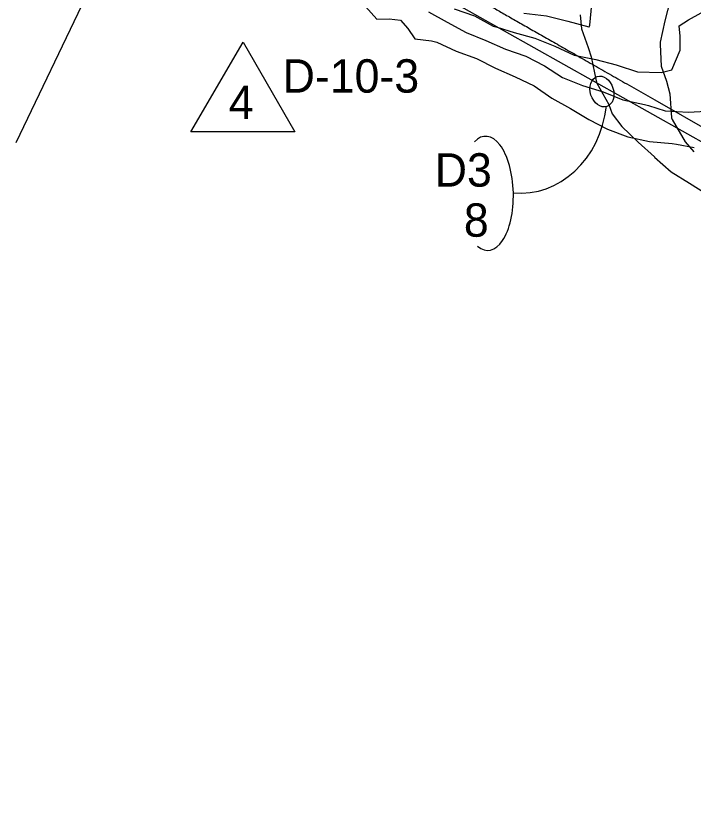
# Model space of a CAD drawing. Extents: x 1638506 to 1658005, y 834807 to 846788.
# Drawn here: x 1640164.8 to 1640408.1, y 842236.7 to 842523.2 of the extents above; entities that cross this region are included whole.
import ezdxf

# ---------------------------------------------------------------- set-up
doc = ezdxf.new("R2010")
doc.units = 0
for name, color, linetype in [('Default', 7, 'Continuous'), ('Old_Level_1', 7, 'Continuous'), ('Old_Level_2', 7, 'Continuous'), ('Scratch_Level_0', 7, 'Continuous')]:
    doc.layers.add(name, color=color, linetype=linetype)

msp = doc.modelspace()

# ---------------------------------------------------------------- linework, layer by layer
at = {"layer": 'Default'}
msp.add_line((1640314.09, 842532.64), (1640637.56, 842350.59), dxfattribs=at)
msp.add_lwpolyline([(1640264.98, 842481.57), (1640227.59, 842481.57), (1640246.42, 842513.84)], close=True, dxfattribs=at)
msp.add_ellipse((1640375.35, 842496.07), major_axis=(-1.72, 5.4), ratio=0.730797, dxfattribs=at)
for centre, major_axis, ratio, start_param, end_param in [((1640347.29, 842494.04), (3.78, 34.34), 0.862742, 3.141593, 4.712389), ((1640333.94, 842459.47), (0.49, -20.52), 0.466223, 1.570796, 3.572354), ((1640333.94, 842459.47), (0.49, -20.52), 0.466223, 5.884886, 7.853982)]:
    msp.add_ellipse(centre, major_axis=major_axis, ratio=ratio, start_param=start_param, end_param=end_param, dxfattribs=at)
at = {"layer": 'Old_Level_1'}
for points in [[(1640408.34, 842538.91), (1640403.52, 842535.72), (1640399.85, 842528.99), (1640397.93, 842521.45), (1640396.24, 842513.79), (1640396.26, 842513.01), (1640396.66, 842505.16), (1640398.51, 842499.74), (1640399.73, 842495.28), (1640400.3, 842486.58), (1640400.57, 842486.05), (1640405.23, 842477.95), (1640408.35, 842474.38)], [(1640367.46, 842523.66), (1640367.95, 842518.54), (1640370.42, 842511.9), (1640371.43, 842508.48), (1640373.26, 842499.89), (1640373.45, 842499.1), (1640377.77, 842491.46), (1640379.06, 842488.04), (1640382.51, 842483.53), (1640388.3, 842477.84), (1640394.21, 842472.54), (1640394.25, 842472.5), (1640400.24, 842467.24), (1640406.77, 842463.14), (1640413.31, 842459.07)]]:
    msp.add_lwpolyline(points, dxfattribs=at)
at = {"layer": 'Old_Level_2'}
for p, q in [((1640319.78, 842802.51), (1640164.82, 842477.58)), ((1640394.38, 842493.02), (1640843.22, 842236.75))]:
    msp.add_line(p, q, dxfattribs=at)
msp.add_open_spline([(1640269.4, 842563.39), (1640311.31, 842540.44), (1640352.83, 842516.74), (1640394.38, 842493.02)], degree=2, dxfattribs=at)
at = {"layer": 'Scratch_Level_0'}
for points in [[(1640290.38, 842526.57), (1640294.52, 842522.1), (1640298.94, 842522.13), (1640302.93, 842521.71), (1640305.57, 842518.68), (1640308.1, 842515.05), (1640314.13, 842514.24), (1640316.04, 842513.75), (1640323.01, 842510.56), (1640330.24, 842507.89), (1640337.06, 842504.44), (1640344.11, 842501.4), (1640350.99, 842498.06), (1640357.32, 842493.65), (1640364, 842489.91), (1640370.6, 842486.02), (1640377.39, 842482.5), (1640384.63, 842479.83), (1640392.38, 842478.16), (1640400.58, 842477.36), (1640402.08, 842477.17), (1640408.49, 842475.99)], [(1640322.3, 842525.81), (1640329.58, 842523.22), (1640336.3, 842519.56), (1640337.67, 842519.25), (1640343.75, 842517.31), (1640351.27, 842515.19), (1640358.42, 842512.36), (1640365.39, 842509.18), (1640373.17, 842507.57), (1640380.4, 842505.67), (1640380.75, 842505.57), (1640388.1, 842503.11), (1640396.59, 842502.87), (1640400.5, 842503.85), (1640403.46, 842510.94), (1640403.39, 842515.96), (1640403.13, 842519.73), (1640406.44, 842521.82), (1640410.95, 842524.29)], [(1640370.75, 842519.31), (1640370.97, 842519.93), (1640371.73, 842527.42)], [(1640313.08, 842524.65), (1640319.78, 842520.94), (1640326.51, 842517.31), (1640333.64, 842514.44), (1640340.65, 842511.34), (1640347.94, 842508.79), (1640354.73, 842505.25), (1640361.17, 842501.06), (1640368.3, 842498.19), (1640375.76, 842495.96), (1640382.86, 842493.03), (1640390.61, 842491.35), (1640392.07, 842490.99), (1640398.07, 842489.11), (1640406.43, 842488.62), (1640412.6, 842488.95)], [(1640347.31, 842524.17), (1640355.43, 842523.21), (1640363.1, 842521.36), (1640370.65, 842519.32), (1640370.75, 842519.31)]]:
    msp.add_lwpolyline(points, dxfattribs=at)

# ---------------------------------------------------------------- texts
at = {"layer": 'Default'}
for s, p in [('D-10-3', (1640260.63, 842495.66)), ('4', (1640241.24, 842486.18)), ('D3', (1640315.27, 842461.88)), ('8', (1640325.73, 842443.88))]:
    msp.add_text(s, height=12, dxfattribs=at).set_placement(p)

doc.saveas('drawing.dxf')
